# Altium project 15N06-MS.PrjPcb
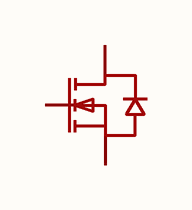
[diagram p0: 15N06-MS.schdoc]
1 sheet, 1 parts. Net scope: global (net labels, ports and power ports of the same name join across sheets).

## Sheet 15N06-MS.schdoc
size 127 x 101 mm

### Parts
Q?  15n06-ms  [SOT-89-3_L4.5-W2.5-P1.50-LS4.0-BR]  (value not drawn)

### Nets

Not connected (* = marked no-connect by the designer): Q? 1(G) 2(D) 3(S)

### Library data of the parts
Q? = 15n06-ms: 数量:1个N沟道;漏源电压(Vdss):60V;连续漏极电流(Id):15A;导通电阻(RDS(on)):26mΩ@10V;耗散功率(Pd):1.5W;阈值电压(Vgs(th)):1.6V;; Manufacturer: MSKSEMI(美森科); AddInBom: yes; ModelId: 8477a6f75bbf4339b92e888630a1da9f; ModelTransform: 157.48,177.165,0,180,0,0,-3.15,0,0; Number: 1个N沟道; Drain to Source Voltage: 60V; Current - Continuous Drain(Id): 15A; Pd - Power Dissipation: 1.5W; Gate Threshold Voltage (Vgs(th)): 1.6V; Gate Charge(Qg): 20.3nC@10V; Input Capacitance(Ciss): 1.148nF; Reverse Transfer Capacitance (Crss@Vds): 49.4pF; Type: N沟道; Output Capacitance(Coss): 58.5pF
